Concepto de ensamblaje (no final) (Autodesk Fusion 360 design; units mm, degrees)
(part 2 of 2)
sketch "Sketch10" plane through (-0.0803, 0, -159.4953) normal (0.0005, 0, 1) x axis (1, 0, -0.0005)
  line L1 (-16.9356, 76.9) -> (-16.9356, 66.35)
  line L2 (-21.2701, 63.8474) -> (-30.4067, 69.1224)
  line L3 (-18.3701, 58.8245) -> (-21.2701, 63.8474)
  line L4 (-32.4701, 34.4026) -> (-18.3701, 58.8245)
  line L5 (-38.2701, 34.4026) -> (-32.4701, 34.4026)
  line L6 (-47.4067, 39.6776) -> (-38.2701, 34.4026)
  line L7 (-38.2701, 29.3974) -> (-47.4067, 24.1224)
  line L8 (-32.4701, 29.3974) -> (-38.2701, 29.3974)
  line L9 (-18.3701, 4.9755) -> (-32.4701, 29.3974)
  line L10 (-21.2701, -0.0474) -> (-18.3701, 4.9755)
  line L11 (-30.4067, -5.3224) -> (-21.2701, -0.0474)
  line L12 (-16.9356, -2.55) -> (-16.9356, -13.1)
  line L13 (-14.0356, 2.4729) -> (-16.9356, -2.55)
  line L14 (14.1644, 2.4729) -> (-14.0356, 2.4729)
  line L15 (17.0644, -2.55) -> (14.1644, 2.4729)
  line L16 (17.0644, -13.1) -> (17.0644, -2.55)
  line L17 (21.399, -0.0474) -> (30.5356, -5.3224)
  line L18 (18.499, 4.9755) -> (21.399, -0.0474)
  line L19 (32.599, 29.3974) -> (18.499, 4.9755)
  line L20 (38.399, 29.3974) -> (32.599, 29.3974)
  line L21 (47.5356, 24.1224) -> (38.399, 29.3974)
  line L22 (38.399, 34.4026) -> (47.5356, 39.6776)
  line L23 (32.599, 34.4026) -> (38.399, 34.4026)
  line L24 (18.499, 58.8245) -> (32.599, 34.4026)
  line L25 (21.399, 63.8474) -> (18.499, 58.8245)
  line L26 (30.5356, 69.1224) -> (21.399, 63.8474)
  line L27 (17.0644, 66.35) -> (17.0644, 76.9)
  line L28 (14.1644, 61.3271) -> (17.0644, 66.35)
  line L29 (-14.0356, 61.3271) -> (14.1644, 61.3271)
  line L30 (-16.9356, 66.35) -> (-14.0356, 61.3271)
  arc A1 centre (0.0644, 31.9) radius 48.1041 clockwise from (-30.4067, 69.1224) to (-16.9356, 76.9)
  arc A2 centre (0.0644, 31.9) radius 48.1041 clockwise from (-47.4067, 24.1224) to (-47.4067, 39.6776)
  arc A3 centre (0.0644, 31.9) radius 48.1041 clockwise from (-16.9356, -13.1) to (-30.4067, -5.3224)
  arc A4 centre (0.0644, 31.9) radius 48.1041 clockwise from (30.5356, -5.3224) to (17.0644, -13.1)
  arc A5 centre (0.0644, 31.9) radius 48.1041 clockwise from (47.5356, 39.6776) to (47.5356, 24.1224)
  arc A6 centre (0.0644, 31.9) radius 48.1041 clockwise from (17.0644, 76.9) to (30.5356, 69.1224)
  circle C1 centre (0.0644, 31.9) radius 10
  circle C2 centre (0.0644, 31.9) radius 10
extrude "Extrude17" cut sketch "Sketch10" profile of C1 C2 against normal blind 29
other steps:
base_feature "Base Feature1"
base_feature "Base Feature1"
base_feature "Base Feature1"
base_feature "Base Feature1"
base_feature "Base Feature1"
base_feature "Base Feature1"
extrude "Extrude4" cut sketch "Sketch10" profile of C1 C2 against normal blind 29
create_component "CreateComponent1"
create_component "CreateComponent2"
create_component "CreateComponent3"
create_component "CreateComponent4"
joint_origin "JointOrigin1" OffsetX 0 OffsetY 0 OffsetZ 0 AngleZ 0
joint_origin "JointOrigin1" OffsetX 0 OffsetY 0 OffsetZ 0 AngleZ 0
joint_origin "JointOrigin1" OffsetX 0 OffsetY 0 OffsetZ 0 AngleZ 0
joint_origin "JointOrigin2" OffsetX 0 OffsetY 0 OffsetZ 0 AngleZ 0
joint_origin "JointOrigin1" OffsetX 0 OffsetY 0 OffsetZ 0 AngleZ 0
joint_origin "JointOrigin3" OffsetX 0 OffsetY 0 OffsetZ 0 AngleZ 0
create_component "CreateComponent5"
create_component "CreateComponent7"
create_component "CreateComponent8"
create_component "CreateComponent9"
create_component "CreateComponent10"
remove_instance "RemoveInstance1"
remove_instance "RemoveInstance2"
remove_instance "RemoveInstance3"
remove_instance "RemoveInstance4"
joint_origin "JointOrigin4" OffsetX 0 OffsetY 0 OffsetZ 0 AngleZ 0
joint_origin "JointOrigin10" OffsetX 0 OffsetY 0 OffsetZ 0 AngleZ 0
joint_origin "JointOrigin3" OffsetX 0 OffsetY 0 OffsetZ 0 AngleZ 0
joint_origin "JointOrigin11" OffsetX 0 OffsetY 0 OffsetZ 0 AngleZ 0
joint_origin "JointOrigin3" OffsetX 0 OffsetY 0 OffsetZ 0 AngleZ 0
joint_origin "JointOrigin12" OffsetX 0 OffsetY 0 OffsetZ 0 AngleZ 0
joint_origin "JointOrigin13" OffsetX 0 OffsetY 0 OffsetZ 0 AngleZ 0
joint_origin "JointOrigin8" OffsetX 0 OffsetY 0 OffsetZ 0 AngleZ 0
create_component "CreateComponent13"
joint_origin "JointOrigin1" OffsetX 0 OffsetY 0 OffsetZ 0 AngleZ 0
joint_origin "JointOrigin10" OffsetX 0 OffsetY 0 OffsetZ 0 AngleZ 0
create_component "CreateComponent14"
joint_origin "JointOrigin11" OffsetX 0 OffsetY 0 OffsetZ 0 AngleZ 0
joint_origin "JointOrigin4" OffsetX 0 OffsetY 0 OffsetZ 0 AngleZ 0
create_component "CreateComponent15"
create_component "CreateComponent16"
create_component "CreateComponent17"
joint_origin "JointOrigin1" OffsetX 0 OffsetY 0 OffsetZ 0 AngleZ 0
joint_origin "JointOrigin1" OffsetX 0 OffsetY 0 OffsetZ 0 AngleZ 0
joint_origin "JointOrigin1" OffsetX 0 OffsetY 0 OffsetZ 0 AngleZ 0
joint_origin "JointOrigin2" OffsetX 0 OffsetY 0 OffsetZ 0 AngleZ 0
joint_origin "JointOrigin2" OffsetX 0 OffsetY 0 OffsetZ 0 AngleZ 0
joint_origin "JointOrigin1" OffsetX 0 OffsetY 0 OffsetZ 0 AngleZ 0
